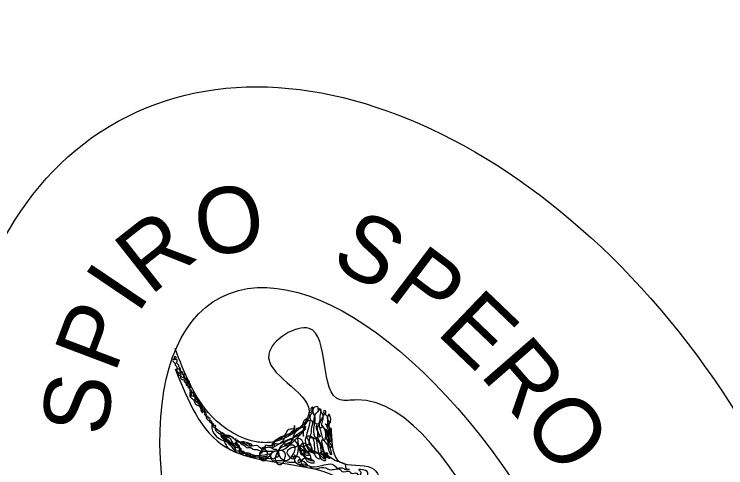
# Model space of a CAD drawing. Extents: x 160093 to 164626, y 177093 to 182727.
# Drawn here: x 162728.73 to 162751.34, y 178264.12 to 178278.55 of the extents above; entities that cross this region are included whole.
import ezdxf

# ---------------------------------------------------------------- set-up
doc = ezdxf.new("R2010")
doc.units = 0
doc.layers.add('Level 38', color=7, linetype='Continuous')
doc.layers.add('Level 40', color=7, linetype='Continuous')

msp = doc.modelspace()

# ---------------------------------------------------------------- linework, layer by layer
at = {"layer": 'Level 38'}
for centre, major_axis, ratio in [((162741.339, 178258.256), (9.304, -16.888), 0.662421), ((162741.077, 178258.344), (5.775, -11.2), 0.456916)]:
    msp.add_ellipse(centre, major_axis=major_axis, ratio=ratio, dxfattribs=at)
for points in [[(162733.843, 178267.269), (162735.477, 178264.761), (162739.619, 178263.302), (162739.91, 178262.777), (162743.877, 178255.077), (162744.052, 178254.552), (162744.519, 178254.552), (162742.244, 178259.511), (162742.419, 178260.502), (162743.41, 178260.677), (162744.402, 178260.152), (162745.044, 178258.986), (162739.619, 178266.277), (162739.093, 178266.277), (162738.102, 178268.552), (162736.818, 178267.736), (162738.102, 178265.927), (162736.935, 178264.936), (162736.468, 178264.936), (162735.01, 178265.752), (162733.843, 178267.911)], [(162734.135, 178267.094), (162734.077, 178267.094), (162734.077, 178267.152), (162734.018, 178267.211), (162734.018, 178267.269), (162733.96, 178267.327), (162733.96, 178267.386), (162733.902, 178267.444), (162733.902, 178267.561), (162733.843, 178267.561), (162733.843, 178267.677), (162733.843, 178267.561), (162733.785, 178267.561), (162733.785, 178267.502), (162733.843, 178267.444), (162733.843, 178267.386), (162733.902, 178267.327), (162733.902, 178267.269), (162733.96, 178267.269), (162734.018, 178267.152), (162734.077, 178267.152), (162734.077, 178267.094), (162734.135, 178267.036), (162734.135, 178266.977), (162734.193, 178266.977), (162734.193, 178266.919), (162734.252, 178266.861), (162734.252, 178266.802), (162734.31, 178266.802), (162734.31, 178266.686), (162734.368, 178266.686), (162734.31, 178266.744), (162734.31, 178266.802), (162733.902, 178267.211), (162733.902, 178267.269), (162733.902, 178267.211), (162734.018, 178267.094), (162734.018, 178266.977), (162734.077, 178266.919), (162734.135, 178266.919), (162734.135, 178266.861), (162734.193, 178266.802), (162734.193, 178266.744), (162734.252, 178266.744), (162734.252, 178266.686), (162734.31, 178266.627), (162734.31, 178266.569), (162734.368, 178266.569), (162734.368, 178266.511), (162734.427, 178266.511), (162734.427, 178266.452), (162734.485, 178266.394), (162734.485, 178266.336), (162734.543, 178266.336), (162734.543, 178266.219), (162734.602, 178266.219), (162734.602, 178266.161), (162734.602, 178266.102), (162734.66, 178266.044), (162734.66, 178265.986), (162734.718, 178265.869), (162734.718, 178265.986), (162734.66, 178266.102), (162734.485, 178266.277), (162734.485, 178266.336), (162734.427, 178266.394), (162734.368, 178266.394), (162734.368, 178266.452), (162734.31, 178266.511), (162734.31, 178266.452), (162734.31, 178266.394), (162734.427, 178266.277), (162734.485, 178266.161), (162734.66, 178265.986), (162734.66, 178265.927), (162734.718, 178265.927), (162734.777, 178265.869), (162734.777, 178265.811), (162734.835, 178265.752), (162734.835, 178265.694), (162734.893, 178265.636), (162734.952, 178265.577), (162735.01, 178265.519), (162735.01, 178265.461), (162735.535, 178264.936), (162735.885, 178264.761), (162735.885, 178264.702), (162736.002, 178264.644), (162736.06, 178264.586), (162736.177, 178264.527), (162736.293, 178264.527), (162736.352, 178264.469), (162736.585, 178264.469), (162736.643, 178264.411), (162736.877, 178264.411), (162736.935, 178264.352), (162737.052, 178264.352)], [(162735.827, 178264.877), (162735.943, 178264.644), (162736.002, 178264.586), (162736.118, 178264.586), (162736.177, 178264.527), (162736.352, 178264.469), (162736.41, 178264.469), (162736.468, 178264.469), (162736.76, 178264.469), (162736.41, 178264.469), (162736.293, 178264.527), (162736.002, 178264.527), (162735.943, 178264.586), (162735.885, 178264.586), (162735.885, 178264.644), (162735.827, 178264.644), (162735.768, 178264.644), (162735.71, 178264.702), (162735.418, 178265.169), (162735.477, 178265.169), (162735.71, 178265.052), (162735.768, 178264.994), (162735.885, 178264.936), (162736.06, 178264.877), (162736.177, 178264.819), (162736.293, 178264.819), (162736.06, 178264.936), (162735.943, 178264.936), (162735.768, 178264.994), (162735.71, 178265.052), (162735.593, 178265.111), (162735.535, 178265.111), (162735.243, 178265.286), (162735.127, 178265.402), (162735.127, 178265.461), (162735.068, 178265.461), (162735.01, 178265.519), (162735.01, 178265.577), (162735.01, 178265.519), (162735.185, 178265.344), (162735.243, 178265.286), (162735.36, 178265.227), (162735.477, 178265.111), (162735.593, 178265.052), (162735.652, 178264.936), (162735.827, 178264.761), (162735.885, 178264.761), (162735.943, 178264.702), (162735.885, 178264.761), (162735.652, 178264.877), (162735.535, 178264.994), (162735.418, 178265.052), (162735.36, 178265.111), (162735.302, 178265.169), (162735.302, 178265.227), (162735.302, 178265.111), (162735.36, 178265.052), (162735.418, 178264.936), (162735.71, 178264.644), (162735.768, 178264.644), (162735.768, 178264.702), (162735.535, 178264.936), (162735.477, 178265.052), (162735.127, 178265.402), (162735.127, 178265.461), (162735.068, 178265.461), (162735.068, 178265.519), (162735.01, 178265.519), (162735.01, 178265.577), (162734.952, 178265.636), (162734.952, 178265.694), (162734.893, 178265.694), (162734.893, 178265.752), (162734.835, 178265.752), (162734.835, 178265.869), (162734.777, 178265.927), (162734.777, 178265.986), (162734.718, 178265.986), (162734.718, 178266.044), (162734.66, 178266.102), (162734.66, 178266.161), (162734.602, 178266.161), (162734.602, 178266.219), (162734.485, 178266.336), (162734.485, 178266.394), (162734.427, 178266.452), (162734.427, 178266.511), (162734.368, 178266.511), (162734.368, 178266.569), (162734.31, 178266.627), (162734.31, 178266.686), (162734.252, 178266.744), (162734.252, 178266.802), (162734.193, 178266.861), (162734.193, 178266.919), (162734.135, 178266.977), (162734.135, 178267.094)], [(162738.685, 178265.519), (162738.743, 178265.519), (162738.743, 178265.811), (162738.743, 178265.402), (162738.802, 178265.344), (162738.802, 178265.286), (162738.743, 178265.461), (162738.743, 178265.577), (162738.685, 178265.694), (162738.685, 178265.752), (162738.627, 178265.811), (162738.627, 178265.927), (162738.568, 178265.927), (162738.568, 178265.869), (162738.51, 178265.694), (162738.452, 178265.577), (162738.452, 178265.402), (162738.51, 178265.402), (162738.51, 178265.461), (162738.51, 178265.519), (162738.51, 178265.869), (162738.393, 178265.986), (162738.393, 178265.927), (162738.335, 178265.869), (162738.335, 178265.519), (162738.393, 178265.519), (162738.452, 178265.636), (162738.452, 178265.752), (162738.452, 178265.986), (162738.393, 178265.986), (162738.393, 178266.044), (162738.277, 178266.044), (162738.218, 178265.986), (162738.218, 178265.869), (162738.16, 178265.811), (162738.16, 178265.636), (162738.218, 178265.577), (162738.218, 178265.519), (162738.218, 178265.577), (162738.277, 178265.636), (162738.218, 178265.986), (162738.218, 178266.044), (162738.16, 178265.986), (162738.16, 178265.869), (162738.102, 178265.869), (162738.102, 178265.694), (162738.043, 178265.694), (162738.043, 178265.636), (162737.927, 178265.519), (162737.868, 178265.461), (162737.81, 178265.402), (162737.693, 178265.344), (162737.635, 178265.286), (162737.577, 178265.286), (162737.46, 178265.169), (162737.402, 178265.169), (162737.343, 178265.111), (162737.285, 178265.111), (162737.168, 178264.994), (162737.052, 178264.994), (162736.993, 178264.936), (162736.935, 178264.936), (162736.935, 178264.877), (162736.877, 178264.819), (162736.702, 178264.819), (162736.702, 178264.761), (162736.527, 178264.761), (162736.468, 178264.819), (162736.235, 178264.819), (162736.177, 178264.877), (162736.06, 178264.877), (162736.002, 178264.936), (162735.885, 178264.936), (162735.827, 178264.994), (162735.768, 178264.994), (162735.768, 178265.052), (162735.768, 178264.994), (162735.885, 178264.936), (162735.943, 178264.877), (162736.06, 178264.819), (162736.118, 178264.761), (162736.235, 178264.761), (162736.352, 178264.702), (162736.41, 178264.702), (162736.585, 178264.644), (162736.702, 178264.644), (162737.285, 178264.702), (162737.46, 178264.819), (162737.985, 178265.344), (162737.868, 178265.227), (162737.693, 178265.111), (162737.402, 178264.994), (162737.168, 178264.877), (162737.052, 178264.819), (162736.935, 178264.761), (162736.935, 178264.819), (162737.227, 178265.111)], [(162737.227, 178265.111), (162737.343, 178265.169), (162737.46, 178265.344), (162737.635, 178265.402), (162737.635, 178265.461), (162737.635, 178265.402), (162737.343, 178265.111), (162737.285, 178264.994), (162737.052, 178264.877), (162736.993, 178264.877), (162736.993, 178264.819), (162736.993, 178264.877), (162737.052, 178264.994), (162737.285, 178265.111), (162737.985, 178265.402), (162737.81, 178265.227), (162737.577, 178265.052), (162737.518, 178264.936), (162737.402, 178264.877), (162737.343, 178264.819), (162737.343, 178264.877), (162737.402, 178264.877), (162737.693, 178265.286), (162737.927, 178265.519), (162737.927, 178265.577), (162738.043, 178265.694), (162737.927, 178265.344), (162737.927, 178265.111), (162737.927, 178265.344), (162738.043, 178265.577), (162738.102, 178265.636), (162738.102, 178265.461), (162738.043, 178265.052), (162738.102, 178264.936), (162738.102, 178264.877), (162738.102, 178264.936), (162738.16, 178265.169), (162738.218, 178265.519), (162738.277, 178265.636), (162738.277, 178265.111), (162738.335, 178265.052), (162738.335, 178265.461), (162738.335, 178265.344), (162738.393, 178265.227), (162738.393, 178265.111), (162738.452, 178265.111), (162738.393, 178265.227), (162738.393, 178265.461), (162738.51, 178265.111), (162738.568, 178264.994), (162738.568, 178265.402), (162738.51, 178265.461), (162738.627, 178265.286), (162738.685, 178265.111), (162738.743, 178265.052), (162738.743, 178265.111), (162738.685, 178265.402), (162738.627, 178265.519), (162738.685, 178265.461), (162738.802, 178265.111), (162738.802, 178265.052), (162738.802, 178265.169), (162738.743, 178265.344), (162738.802, 178264.936), (162738.743, 178265.052), (162738.685, 178265.286), (162738.627, 178265.344), (162738.685, 178265.169), (162738.743, 178264.936), (162738.802, 178264.819), (162738.802, 178264.761), (162738.743, 178264.819), (162738.685, 178265.169), (162738.627, 178265.227), (162738.627, 178265.169), (162738.743, 178264.819), (162738.802, 178264.527), (162738.743, 178264.644), (162738.627, 178264.936), (162738.51, 178264.994), (162738.51, 178264.877), (162738.568, 178264.644), (162738.627, 178264.469), (162738.627, 178264.411), (162738.568, 178264.586), (162738.335, 178265.052), (162738.335, 178264.994), (162738.393, 178264.644), (162738.568, 178264.352), (162738.627, 178264.352), (162738.568, 178264.469), (162738.452, 178264.877), (162738.277, 178265.052), (162738.102, 178265.052), (162738.16, 178264.819), (162738.218, 178264.644), (162738.277, 178264.586)], [(162738.277, 178264.586), (162738.277, 178264.819), (162738.16, 178265.111), (162738.043, 178265.111), (162738.043, 178264.761), (162738.16, 178264.644), (162738.16, 178264.819), (162737.927, 178264.761), (162737.985, 178264.586), (162737.752, 178264.819), (162737.81, 178264.644), (162737.868, 178264.527), (162737.927, 178264.527), (162737.927, 178264.819), (162737.868, 178264.994), (162737.752, 178265.052), (162737.752, 178264.877), (162737.752, 178264.819), (162737.81, 178264.702), (162738.043, 178264.644), (162738.16, 178264.644), (162738.043, 178264.819), (162737.985, 178264.877), (162737.868, 178264.877), (162737.868, 178264.586), (162737.985, 178264.527), (162738.102, 178264.527), (162738.043, 178264.644), (162737.927, 178264.761), (162737.752, 178264.819), (162737.635, 178264.761), (162737.577, 178264.761), (162737.46, 178264.702), (162737.402, 178264.644), (162737.635, 178264.411), (162737.693, 178264.469), (162737.752, 178264.644), (162737.752, 178264.819), (162737.693, 178264.936), (162737.635, 178264.994), (162737.46, 178264.994), (162737.343, 178264.936), (162737.227, 178264.819), (162737.168, 178264.761), (162737.168, 178264.469), (162737.227, 178264.411), (162737.343, 178264.352), (162737.635, 178264.819), (162737.402, 178264.819), (162737.227, 178264.761), (162737.11, 178264.644), (162737.052, 178264.527), (162737.052, 178264.294), (162737.11, 178264.236), (162737.227, 178264.236), (162737.285, 178264.294), (162737.343, 178264.469), (162737.343, 178264.586), (162736.877, 178264.527), (162736.877, 178264.469), (162736.935, 178264.411), (162736.993, 178264.411), (162737.052, 178264.469), (162737.11, 178264.469), (162737.11, 178264.586), (162737.052, 178264.702), (162736.993, 178264.702), (162736.877, 178264.761), (162736.76, 178264.761), (162736.643, 178264.702), (162736.585, 178264.586), (162736.527, 178264.527), (162736.527, 178264.411), (162736.702, 178264.352), (162736.76, 178264.469), (162736.76, 178264.644), (162736.702, 178264.702), (162736.702, 178264.761), (162736.643, 178264.761), (162736.585, 178264.702), (162736.585, 178264.644), (162736.527, 178264.586), (162736.527, 178264.527), (162736.527, 178264.469), (162736.585, 178264.411), (162736.702, 178264.411), (162736.877, 178264.527), (162736.293, 178264.527), (162736.177, 178264.586), (162736.118, 178264.586), (162735.885, 178264.702), (162735.885, 178264.761), (162735.827, 178264.819), (162735.827, 178264.877), (162735.768, 178264.877), (162735.768, 178264.936), (162735.827, 178264.877)], [(162738.802, 178265.286), (162739.093, 178264.294), (162740.085, 178264.119), (162740.727, 178262.602), (162742.244, 178261.786), (162742.069, 178259.802), (162742.069, 178258.344), (162741.602, 178259.977), (162741.427, 178260.969)], [(162737.052, 178264.352), (162737.168, 178264.352), (162737.227, 178264.352), (162737.46, 178264.294), (162737.635, 178264.294), (162737.752, 178264.236), (162737.985, 178264.236), (162738.102, 178264.177), (162738.452, 178264.177), (162738.918, 178264.177), (162738.977, 178264.119), (162739.152, 178264.119), (162739.268, 178264.061), (162739.385, 178264.061), (162739.327, 178264.061), (162739.268, 178264.119), (162739.268, 178264.177), (162739.093, 178264.294), (162738.918, 178264.352), (162738.743, 178264.469), (162738.568, 178264.527), (162738.102, 178264.644), (162738.16, 178264.644), (162738.393, 178264.411), (162738.452, 178264.411), (162738.452, 178264.469), (162738.51, 178264.644), (162738.743, 178264.411), (162738.685, 178264.469), (162738.685, 178264.586), (162738.627, 178264.586), (162738.627, 178264.527), (162738.627, 178264.411), (162738.277, 178264.644), (162738.102, 178264.644), (162737.927, 178264.586), (162737.927, 178264.527), (162737.985, 178264.469), (162738.16, 178264.352), (162738.218, 178264.352), (162738.16, 178264.411), (162738.16, 178264.469), (162738.043, 178264.586), (162737.985, 178264.586), (162737.927, 178264.527), (162737.985, 178264.411), (162738.102, 178264.294), (162738.277, 178264.294), (162738.218, 178264.352), (162737.868, 178264.352), (162737.868, 178264.236), (162738.043, 178264.177), (162737.868, 178264.352), (162737.752, 178264.352), (162737.752, 178264.294), (162737.81, 178264.294), (162737.81, 178264.411), (162737.752, 178264.469), (162737.693, 178264.469), (162737.635, 178264.527), (162737.635, 178264.469), (162737.577, 178264.469), (162737.635, 178264.411), (162737.635, 178264.352), (162737.752, 178264.236), (162737.868, 178264.177), (162737.985, 178264.177), (162738.102, 178264.177), (162738.16, 178264.119), (162738.627, 178264.119), (162738.743, 178264.061), (162739.093, 178264.061), (162739.152, 178264.002), (162739.385, 178264.002), (162739.444, 178263.944), (162739.619, 178263.944), (162739.677, 178263.886), (162739.735, 178263.886), (162739.735, 178263.827), (162739.794, 178263.827), (162739.91, 178263.711), (162739.969, 178263.711), (162739.969, 178263.652), (162740.027, 178263.594), (162740.085, 178263.594), (162740.085, 178263.652), (162740.027, 178263.711), (162740.027, 178263.827), (162739.969, 178263.886), (162739.969, 178263.944), (162739.735, 178264.061), (162739.677, 178264.061), (162739.735, 178264.002), (162739.735, 178263.886), (162739.852, 178263.769), (162739.969, 178263.769), (162739.969, 178263.886)]]:
    msp.add_spline(points, degree=3, dxfattribs=at)

# ---------------------------------------------------------------- texts
at = {"layer": 'Level 40'}
for s, rotation, p in [('O', 8.6887, (162734.625, 178270.801)), ('R', 38.216, (162733.051, 178269.572)), ('S', 331.8059, (162738.726, 178270.581)), ('P', 322.8559, (162740.502, 178269.626)), ('I', 55.952, (162732.641, 178268.97)), ('E', 316.2411, (162742.109, 178268.406)), ('P', 69.233, (162731.924, 178267.09)), ('R', 311.0144, (162743.494, 178267.078)), ('S', 82.4334, (162731.655, 178265.091)), ('O', 306.3644, (162744.818, 178265.554))]:
    msp.add_text(s, height=2.1, rotation=rotation, dxfattribs=at).set_placement(p)

doc.saveas('drawing.dxf')
